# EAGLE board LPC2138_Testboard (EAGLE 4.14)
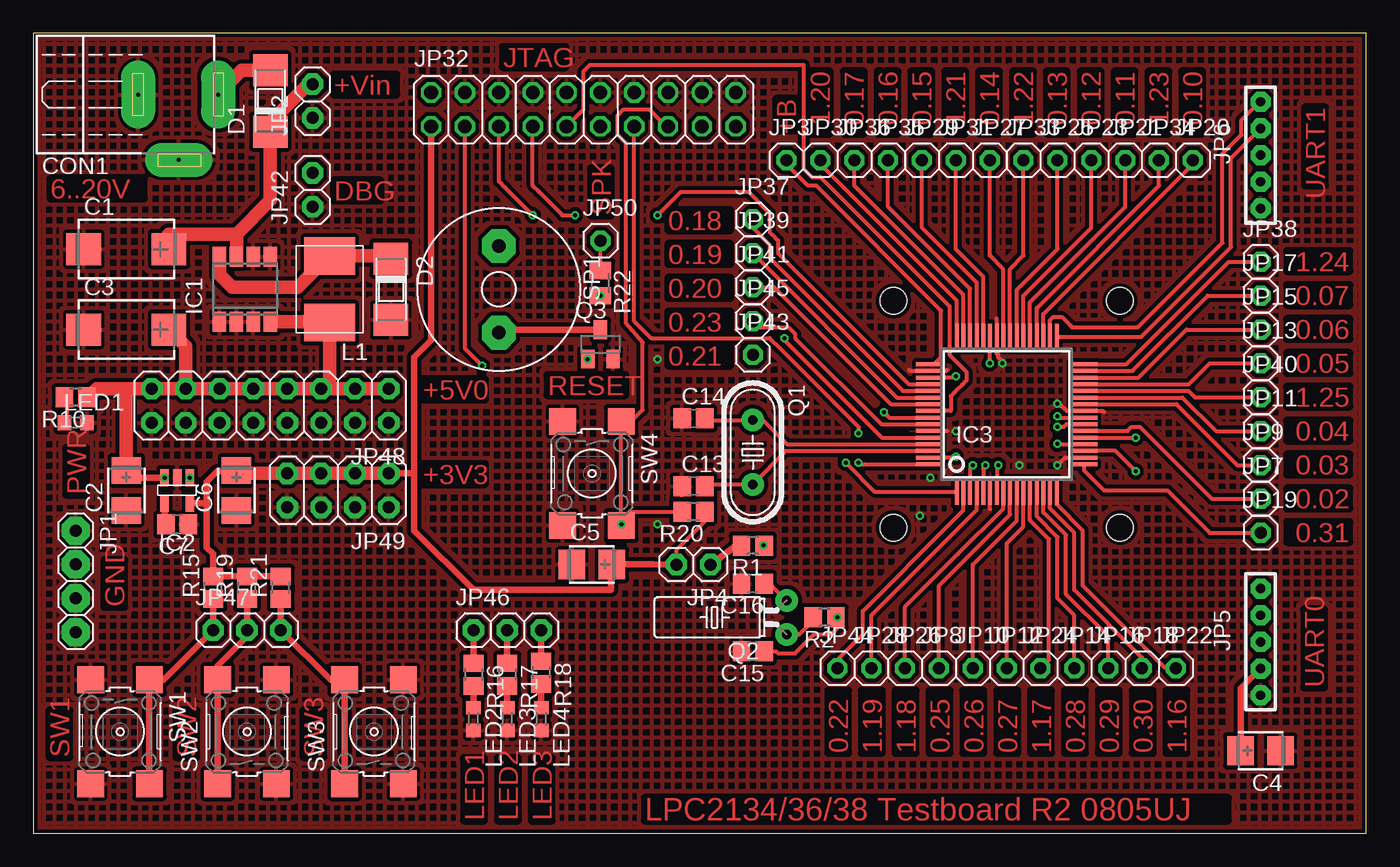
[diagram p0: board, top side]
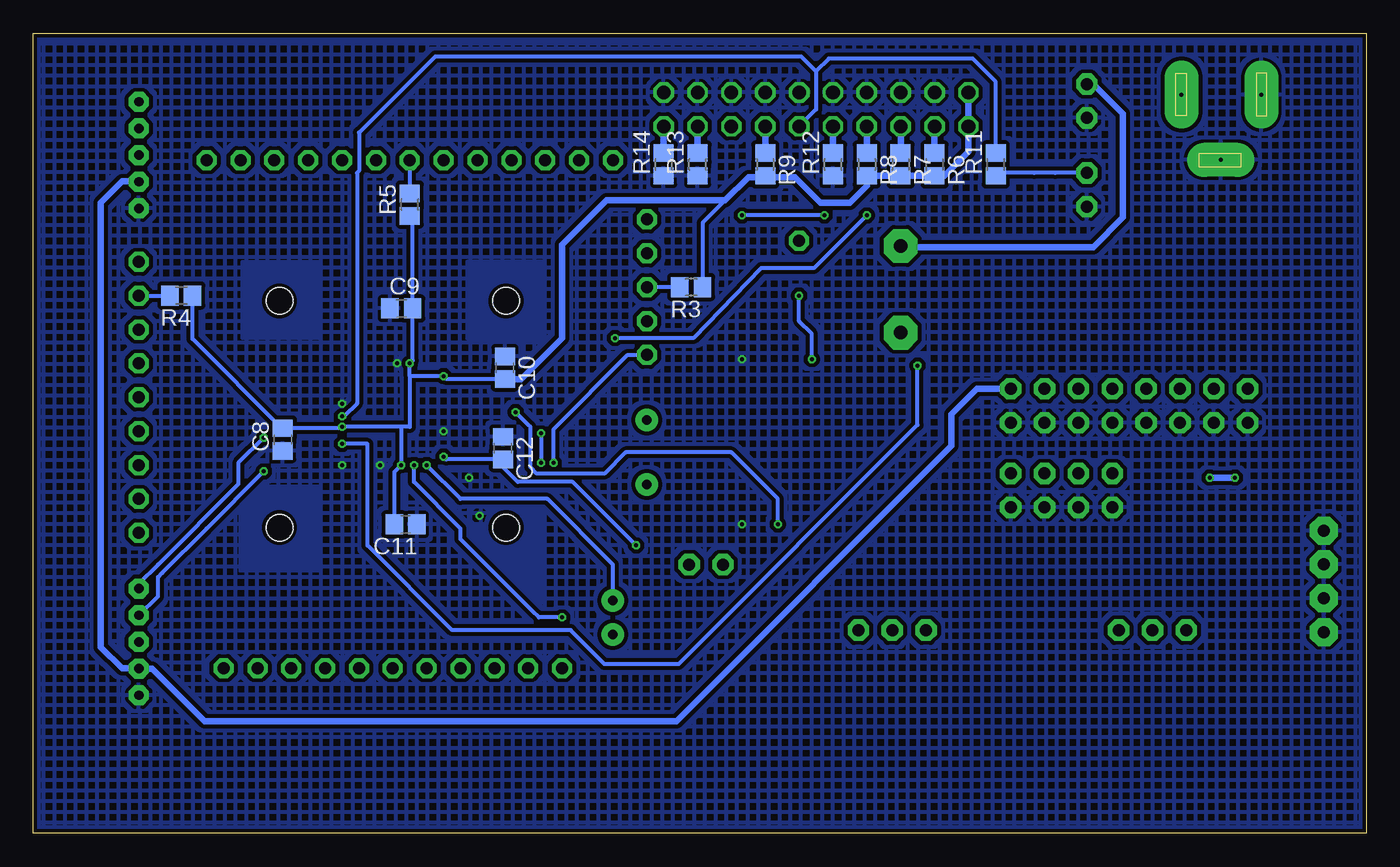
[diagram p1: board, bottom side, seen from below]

Size 100 x 60 mm. Coordinates in mm from the lower left corner, seen from the top.
Outline: 0,0 100,0 100,60 0,60 0,0
Copper layers (1*16): Top 0.035mm / dielectric 1.5mm / Bottom 0.035mm
Design rules "default": minimum track width 0.3mm, minimum drill 0.3mm, track to track 0.3mm, track to pad 0.3mm, pad to pad 0.3mm, via to via 0.3mm, smd to smd 0.3mm, copper to edge 0.3mm, drill to drill 0.3mm, minimum pad ring 10mil, minimum via ring 0.15mm, stop-mask expansion 4mil, vias tented up to drill 0mil, thermal gap 10mil
Net classes: 0 default: width 0.3 mm, drill 0.3 mm, clearance 0.3 mm; 1 power: width 0.6 mm, drill 0.3 mm, clearance 0.6 mm; 2 power_UB: width 1.27 mm, drill 0.25 mm, clearance 0.6 mm

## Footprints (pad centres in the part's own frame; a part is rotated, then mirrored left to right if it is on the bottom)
CT7343 = smd 2.6 x 2.4: + 3.2,0; - -3.2,0
CT3528 = smd 2 x 2.2: + 1.5,0; - -1.5,0
C0805 = smd 1.3 x 1.5: 1 -0.85,0; 2 0.85,0
NEB21R = drill 0.3 pad 2.54 long: + 0,7.35; - 0,1.35; C 4.9,4.4
SOD106A = smd 2.4 x 2.6: A 2.3,0; K -2.3,0
SO8_SMALL = smd 1 x 1.5: 1 -1.905,-2.441; 2 -0.635,-2.441; 3 0.635,-2.441; 4 1.905,-2.441; 5 1.905,2.441; 6 0.635,2.441; 7 -0.635,2.441; 8 -1.905,2.441
SOT23-5 = smd 0.635 x 1.27: 1 -0.953,-0.953; 2 0,-0.953; 3 0.953,-0.953; 4 0.953,0.953; 5 -0.953,0.953
SQFP-S-10X10-64 = smd 0.3 x 2: 1 -3.75,-5.8; 2 -3.25,-5.8; 3 -2.75,-5.8; 4 -2.25,-5.8; 5 -1.75,-5.8; 6 -1.25,-5.8; 7 -0.75,-5.8; 8 -0.25,-5.8; 9 0.25,-5.8; 10 0.75,-5.8; 11 1.25,-5.8; 12 1.75,-5.8; 13 2.25,-5.8; 14 2.75,-5.8; 15 3.25,-5.8; 16 3.75,-5.8; 33 3.75,5.8; 34 3.25,5.8; 35 2.75,5.8; 36 2.25,5.8; 37 1.75,5.8; 38 1.25,5.8; 39 0.75,5.8; 40 0.25,5.8; 41 -0.25,5.8; 42 -0.75,5.8; 43 -1.25,5.8; 44 -1.75,5.8; 45 -2.25,5.8; 46 -2.75,5.8; 47 -3.25,5.8; 48 -3.75,5.8 | smd 2 x 0.3: 17 5.8,-3.75; 18 5.8,-3.25; 19 5.8,-2.75; 20 5.8,-2.25; 21 5.8,-1.75; 22 5.8,-1.25; 23 5.8,-0.75; 24 5.8,-0.25; 25 5.8,0.25; 26 5.8,0.75; 27 5.8,1.25; 28 5.8,1.75; 29 5.8,2.25; 30 5.8,2.75; 31 5.8,3.25; 32 5.8,3.75; 49 -5.8,3.75; 50 -5.8,3.25; 51 -5.8,2.75; 52 -5.8,2.25; 53 -5.8,1.75; 54 -5.8,1.25; 55 -5.8,0.75; 56 -5.8,0.25; 57 -5.8,-0.25; 58 -5.8,-0.75; 59 -5.8,-1.25; 60 -5.8,-1.75; 61 -5.8,-2.25; 62 -5.8,-2.75; 63 -5.8,-3.25; 64 -5.8,-3.75 | hole 2: 8.5,8.5; -8.5,8.5; -8.5,-8.5; 8.5,-8.5
1X04 = drill 0.9 pad 2.1 octagon: 1 -3.81,0; 2 -1.27,0; 3 1.27,0; 4 3.81,0
1X02 = drill 0.9 pad 1.6 octagon: 1 -1.27,0; 2 1.27,0
1X01 = drill 0.9 pad 1.5 octagon: 1 0,0
2.00_1X5 = drill 0.7 pad 1.5 octagon: 1 -6,0; 2 -4,0; 3 -2,0; 4 0,0; 5 2,0
2X10 = drill 1.016 pad 1.5 octagon: 1 -11.43,-1.27; 2 -11.43,1.27; 3 -8.89,-1.27; 4 -8.89,1.27; 5 -6.35,-1.27; 6 -6.35,1.27; 7 -3.81,-1.27; 8 -3.81,1.27; 9 -1.27,-1.27; 10 -1.27,1.27; 11 1.27,-1.27; 12 1.27,1.27; 13 3.81,-1.27; 14 3.81,1.27; 15 6.35,-1.27; 16 6.35,1.27; 17 8.89,-1.27; 18 8.89,1.27; 19 11.43,-1.27; 20 11.43,1.27
1X03 = drill 0.9 pad 1.6 octagon: 1 -2.54,0; 2 0,0; 3 2.54,0
2X08 = drill 0.9 pad 1.6 octagon: 1 -8.89,-1.27; 2 -8.89,1.27; 3 -6.35,-1.27; 4 -6.35,1.27; 5 -3.81,-1.27; 6 -3.81,1.27; 7 -1.27,-1.27; 8 -1.27,1.27; 9 1.27,-1.27; 10 1.27,1.27; 11 3.81,-1.27; 12 3.81,1.27; 13 6.35,-1.27; 14 6.35,1.27; 15 8.89,-1.27; 16 8.89,1.27
2X04 = drill 0.9 pad 1.6 octagon: 1 -3.81,-1.27; 2 -3.81,1.27; 3 -1.27,-1.27; 4 -1.27,1.27; 5 1.27,-1.27; 6 1.27,1.27; 7 3.81,-1.27; 8 3.81,1.27
L5550 = smd 3.8 x 2.8: P$1 0,2.5; P$2 0,-2.5
0603 = smd 1 x 1.1: 1 -0.85,0; 2 0.85,0
HC49/S = drill 0.7 pad 1.7 round: 1 -2.413,0; 2 2.413,0
TC38H = drill 0.7 pad 1.7 round: 1 -1.27,0; 2 1.27,0
SOT23 = smd 1 x 1.4: 1 -0.95,-1.1; 2 0.95,-1.1; 3 0,1.1
R0805 = smd 1.3 x 1.5: 1 -0.85,0; 2 0.85,0
M0805 = smd 1.3 x 1.6: 1 -0.95,0; 2 0.95,0
AL60P = drill 1.016 pad 2.54 octagon: 1 -3.251,0; 2 3.251,0
DIGI_SWITCH = smd 2 x 2: 1 3.9,-2.2; 2 -3.9,-2.2; 3 3.9,2.2; 4 -3.9,2.2

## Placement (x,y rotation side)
C1  100µ  [CT7343]  6.99,43.82 0 top
C2  33µ  [CT3528]  6.99,25.72 90 top
C3  470µ  [CT7343]  6.99,37.78 0 top
C4  10µ  [CT3528]  92.08,6.19 180 top
C5  10µ  [CT3528]  41.91,20.16 0 top
C6  10µ  [CT3528]  15.24,25.72 90 top
C7  100n  [C0805]  10.79,23.18 180 top
C8  220n  [C0805]  81.28,29.53 90 bottom
C9  220n  [C0805]  72.39,39.37 0 bottom
C10  220n  [C0805]  64.61,34.92 270 bottom
C11  220n  [C0805]  72.07,23.18 180 bottom
C12  220n  [C0805]  64.77,28.89 270 bottom
C13  22p  [C0805]  49.53,26.04 0 top
C14  22p  [C0805]  49.53,31.12 0 top
C15  22p  [C0805]  53.98,13.65 180 top
C16  22p  [C0805]  53.98,18.73 180 top
CON1  NEB21R  [NEB21R]  6.51,55.41 270 top
D1  MBR1201  [SOD106A]  17.78,54.93 90 top
D2  MBR1201  [SOD106A]  26.83,40.8 270 top
IC1  LM2594-5  [SO8_SMALL]  15.88,40.8 0 top
IC2  LP2992-3.3  [SOT23-5]  10.79,25.72 180 top
IC3  LPC2138  [SQFP-S-10X10-64]  73.03,31.43 0 top
JP1  [1X04]  3.17,18.89 270 top
JP2  [1X02]  20.95,54.92 90 top
JP3  +BAT  [1X01]  56.52,50.48 0 top
JP4  VREF  [1X02]  49.53,20.16 180 top
JP5  UART0  [2.00_1X5]  92.08,16.35 90 top
JP6  UART1  [2.00_1X5]  92.08,52.86 90 top
JP7  [1X01]  92.08,25.09 0 top
JP8  [1X01]  67.94,12.38 0 top
JP9  [1X01]  92.08,27.62 0 top
JP10  [1X01]  70.48,12.38 0 top
JP11  [1X01]  92.08,30.16 0 top
JP12  [1X01]  73.03,12.38 0 top
JP13  [1X01]  92.08,35.24 0 top
JP14  [1X01]  78.11,12.38 0 top
JP15  [1X01]  92.08,37.78 0 top
JP16  [1X01]  80.64,12.38 0 top
JP17  [1X01]  92.08,40.33 0 top
JP18  [1X01]  83.19,12.38 0 top
JP19  [1X01]  92.08,22.55 0 top
JP20  [1X01]  87,50.48 0 top
JP21  [1X01]  81.92,50.48 0 top
JP22  [1X01]  85.72,12.38 0 top
JP23  [1X01]  79.38,50.48 0 top
JP24  [1X01]  75.56,12.38 0 top
JP25  [1X01]  76.83,50.48 0 top
JP26  [1X01]  65.41,12.38 0 top
JP27  [1X01]  71.75,50.48 0 top
JP28  [1X01]  62.87,12.38 0 top
JP29  [1X01]  66.67,50.48 0 top
JP30  [1X01]  59.05,50.48 0 top
JP31  [1X01]  69.22,50.48 0 top
JP32  JTAG  [2X10]  41.27,54.3 0 top
JP33  [1X01]  74.3,50.48 0 top
JP34  [1X01]  84.45,50.48 0 top
JP35  [1X01]  64.14,50.48 0 top
JP36  [1X01]  61.59,50.48 0 top
JP37  [1X01]  53.98,46.04 0 top
JP38  [1X01]  92.08,42.87 0 top
JP39  [1X01]  53.98,43.5 0 top
JP40  [1X01]  92.08,32.7 0 top
JP41  [1X01]  53.98,40.96 0 top
JP42  DBG  [1X02]  20.95,48.26 90 top
JP43  [1X01]  53.98,35.88 0 top
JP44  [1X01]  60.33,12.38 0 top
JP45  [1X01]  53.98,38.42 0 top
JP46  LED  [1X03]  35.56,15.24 0 top
JP47  [1X03]  16.03,15.24 0 top
JP48  [2X08]  17.78,32.07 180 top
JP49  [2X04]  22.86,25.72 180 top
JP50  [1X01]  42.55,44.45 0 top
L1  100µ  [L5550]  22.23,40.8 180 top
LED1  Grün  [0603]  3.17,30.8 0 top
LED2  Gelb  [0603]  33.02,8.57 270 top
LED3  Gelb  [0603]  35.56,8.57 270 top
LED4  Gelb  [0603]  38.1,8.57 270 top
Q1  10M  [HC49/S]  53.98,28.58 270 top
Q2  32768  [TC38H]  56.52,16.2 90 top
Q3  BC847  [SOT23]  42.55,36.67 0 top
R1  10  [R0805]  53.98,21.59 180 top
R2  560k  [R0805]  59.37,16.2 180 top
R3  10k  [R0805]  50.64,40.96 180 bottom
R4  10k  [R0805]  88.9,40.32 180 bottom
R5  10k  [R0805]  71.75,47.15 90 bottom
R6  [R0805]  32.39,50.16 270 bottom
R7  [R0805]  34.93,50.16 270 bottom
R8  [R0805]  37.47,50.16 270 bottom
R9  [R0805]  45.09,50.16 270 bottom
R10  330  [R0805]  3.17,32.7 180 top
R11  [R0805]  27.78,50.16 90 bottom
R12  [R0805]  40,50.16 90 bottom
R13  [R0805]  50.16,50.16 90 bottom
R14  [R0805]  52.7,50.16 90 bottom
R15  10k  [R0805]  13.49,18.42 90 top
R16  680  [R0805]  33.02,11.91 270 top
R17  680  [R0805]  35.56,11.91 270 top
R18  680  [R0805]  38.1,12.06 270 top
R19  10k  [R0805]  16.03,18.42 90 top
R20  10k  [R0805]  49.53,24.13 180 top
R21  10k  [R0805]  18.57,18.42 90 top
R22  4k7  [M0805]  42.55,41.27 270 top
SP1  AL60P  [AL60P]  34.93,40.8 270 top
SW1  [DIGI_SWITCH]  6.51,7.62 90 top
SW2  [DIGI_SWITCH]  16.03,7.62 270 top
SW3  [DIGI_SWITCH]  25.56,7.62 270 top
SW4  RESET  [DIGI_SWITCH]  41.91,26.99 90 top

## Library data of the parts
C1-C16 R1-R22 = rcl
CON1 JP5 JP6 = Connectors
D1 D2 = telefunken
IC1 IC2 = Power
IC3 = lpc213x
JP1-JP4 JP7-JP50 = PinHeaders
L1 LED1-LED4 = OWN
Q1 Q2 = crystal
Q3 = transistor-npn
SP1 = buzzer
SW1-SW4 = Copter

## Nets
+3V3: C5.+ C6.+ C8.2 C9.2 C10.2 C11.2 IC2.5 IC3.7 IC3.23 IC3.43 IC3.51 JP4.2 JP32.1 JP32.2 JP49.1 JP49.3 JP49.5 JP49.7 R3.1 R4.1 R5.1 R6.2 R7.2 R8.2 R9.2 R15.2 R19.2 R20.1 R21.2
+3V3_VREF: JP4.1 R1.2
+5V: C2.+ C3.+ C4.+ IC1.4 IC2.1 IC2.3 JP5.2 JP6.2 JP48.1 JP48.3 JP48.5 JP48.7 JP48.9 JP48.11 JP48.13 JP48.15 L1.P$1 R10.1
+UB: IC3.49 JP3.1
BP_3V3: C7.2 IC2.4
D2 [power]: D2.K IC1.8 L1.P$2
DBG_RTCK: JP42.2 R11.1
GND: C1.- C2.- C3.- C4.- C5.- C6.- C7.1 C8.1 C9.1 C10.1 C11.1 C12.1 C13.1 C14.1 C15.2 C16.2 CON1.- CON1.C D2.A IC1.1 IC1.2 IC1.3 IC1.5 IC1.6 IC2.2 IC3.6 IC3.18 IC3.25 IC3.42 IC3.50 IC3.59 JP1.1 JP1.2 JP1.3 JP1.4 JP2.1 JP5.1 JP6.1 JP32.4 JP32.6 JP32.8 JP32.10 JP32.12 JP32.14 JP32.16 JP32.18 JP32.20 JP42.1 JP48.2 JP48.4 JP48.6 JP48.8 JP48.10 JP48.12 JP48.14 JP48.16 JP49.2 JP49.4 JP49.6 JP49.8 LED1.2 LED2.2 LED3.2 LED4.2 Q3.2 R12.1 R13.1 R14.1 SW1.3 SW1.4 SW2.3 SW2.4 SW3.3 SW3.4 SW4.3 SW4.4
JTAG_17: JP32.17 R13.2
JTAG_19: JP32.19 R14.2
LED1: JP46.1 R16.1
LED1_A1: LED4.1 R18.2
LED1_A2: LED1.1 R10.2
LED2_A1: LED3.1 R17.2
LED3_A1: LED2.1 R16.2
LED5: JP46.2 R17.1
LED6: JP46.3 R18.1
P0.0_TXD0: IC3.19 JP5.4
P0.1_RXD0: IC3.21 JP5.5
P0.2_SCL0: IC3.22 JP7.1
P0.3_SDA0: IC3.26 JP9.1
P0.4_SCK0: IC3.27 JP11.1
P0.5_MISO0: IC3.29 JP13.1
P0.6_MOSI0: IC3.30 JP15.1
P0.7_SSEL0: IC3.31 JP17.1 R4.2
P0.8_TXD1: IC3.33 JP6.4
P0.9_RXD1: IC3.34 JP6.5
P0.10: IC3.35 JP20.1
P0.11_SCL1: IC3.37 JP21.1
P0.12_MAT1.0: IC3.38 JP23.1
P0.13: IC3.39 JP25.1
P0.14_SDA1: IC3.41 JP27.1 R5.2
P0.15_EINT2: IC3.45 JP29.1
P0.16_EINT0: IC3.46 JP35.1
P0.17_SCK1: IC3.47 JP36.1
P0.18_MISO1: IC3.53 JP37.1
P0.19_MOSI1: IC3.54 JP39.1
P0.20_SSEL1: IC3.55 JP41.1 R3.2
P0.21_PWM5: IC3.1 JP43.1
P0.22: IC3.2 JP44.1
P0.23: IC3.58 JP45.1
P0.25_AD0.4: IC3.9 JP8.1
P0.26_AD0.5: IC3.10 JP10.1
P0.27_AD0.0: IC3.11 JP12.1
P0.28_AD0.1: IC3.13 JP14.1
P0.29_AD0.2: IC3.14 JP16.1
P0.30_AD0.3: IC3.15 JP18.1
P0.31: IC3.17 JP19.1
P1.16: IC3.16 JP22.1
P1.17: IC3.12 JP24.1
P1.18: IC3.8 JP26.1
P1.19: IC3.4 JP28.1
P1.20: IC3.48 JP30.1
P1.21: IC3.44 JP31.1
P1.22: IC3.40 JP33.1
P1.23: IC3.36 JP34.1
P1.24: IC3.32 JP38.1
P1.25: IC3.28 JP40.1
P1.26_RTCK: IC3.24 JP32.11 R11.2
P1.27_TDO: IC3.64 JP32.13 R9.1
P1.28_TDI: IC3.60 JP32.5 R7.1
P1.29_TCK: IC3.56 JP32.9 R12.2
P1.30_TMS: IC3.52 JP32.7 R8.1
P1.31_TRST: IC3.20 JP32.3 R6.1
Q1B: Q3.1 R22.2
RQ: Q2.1 R2.2
RST: IC3.57 JP32.15 R20.2 SW4.1 SW4.2
RTXC1: C16.1 IC3.3 Q2.2
RTXC2: C15.1 IC3.5 R2.1
S1: JP47.3 R21.1 SW3.1 SW3.2
S5: JP47.2 R19.1 SW2.1 SW2.2
S6: JP47.1 R15.1 SW1.1 SW1.2
SPK_GND: Q3.3 SP1.2
SPK_IN: JP50.1 R22.1
VIN [power]: CON1.+ D1.A
VIN_D [power]: C1.+ D1.K IC1.7 JP2.2 SP1.1
VREF: C12.2 IC3.63 R1.1
XTAL1: C13.2 IC3.62 Q1.2
XTAL2: C14.2 IC3.61 Q1.1

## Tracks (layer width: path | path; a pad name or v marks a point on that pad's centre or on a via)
+3V3  (via drill 0.3 pad 0.6)
  Top 0.3: IC3.7 72.28,27.51 v72.39,27.62 | IC3.43 71.78,35.26 v71.75,35.24 | IC3.51 69.11,34.19 v69.22,34.29 | IC3.23 77.52,30.68 77.31,30.48 v76.83,30.48 | R20.1 50.38,23.39 48.26,21.27 JP4.2
  Top 0.5: JP4.2 46.51,20.16 C5.+ 43.41,19.84 43.34,19.84 43.34,18.26 33.02,18.26 28.57,22.7 28.57,26.99 | IC2.5 12.23,24.77 13.02,24.77 | C6.+ 15.08,27.22 15.08,27.15 13.81,27.15 13.02,26.35 13.02,24.77 | R21.2 18.57,19.21 18.52,19.27 R19.2 16.03,19.21 15.97,19.27 R15.2 13.49,20.95 13.02,21.43 13.02,24.77 | JP49.1 28.57,26.99 | JP32.1 29.84,53.18 JP32.1 29.84,52.7 29.84,36.99 28.57,35.72 28.57,26.99
  Top 1: JP49.1 JP49.3 JP49.5 JP49.7 15.4,26.99 15.24,27.15 C6.+
  Bottom 0.3: C11.2 72.92,27.09 v72.39,27.62 72.39,30.48 | C10.2 69,34.08 v69.22,34.29 71.75,34.29 | 72.39,30.48 v76.83,30.48 76.94,30.38 C8.2 81.28,30.32 88.05,37.09 R4.1 | 71.75,34.29 v71.75,35.24 71.54,35.46 C9.2 71.54,46.14 71.75,46.35 | 71.75,34.29 71.75,30.48 72.39,30.48 | R3.1 49.79,45.78 48.1,47.47 | 71.75,46.35 | 71.75,46.35 R5.1
  Bottom 0.5: JP32.2 JP32.1 29.84,51.12 31.65,49.31 R6.2 34.82,49.31 34.92,49.21 34.93,49.21 R7.2 37.36,49.31 37.47,49.21 R8.2 37.47,48.58 38.73,47.31 40.96,47.31 42.86,49.21 45.09,49.21 | C10.2 63.4,34.08 60.33,37.15 60.33,44.13 56.99,47.47 48.1,47.47 46.35,49.21 45.09,49.21 | 45.09,49.21 R9.2
+3V3_VREF
  Top 0.5: R1.2 52.7,21.59 JP4.1
+5V  (via drill 0.3 pad 0.6)
  Top 0.3: IC2.1 | IC2.3 9.68,26.67 IC2.3
  Top 0.5: IC2.3 7.62,26.67 6.99,27.3 | 92.08,12.38 | JP5.2 92.08,12.38 | C4.+ 90.58,10.88 92.08,12.38
  Top 1: JP48.13 11.27,33.34 JP48.15 6.99,33.34 | JP48.13 JP48.11 JP48.9 JP48.7 JP48.5 | JP48.1 JP48.3 JP48.5 | C3.+ 10.32,37.62 11.43,36.51 JP48.13 | R10.1 4.13,32.7 4.76,33.34 6.99,33.34 | C2.+ 6.99,27.3 6.99,33.34 | IC1.4 22.12,38.36 22.23,38.26 L1.P$1 22.23,33.97 JP48.5
  Bottom 0.5: JP48.1 29.21,33.34 31.11,31.43 31.11,29.05 | IC2.3 IC2.1 | 92.08,12.38 | 92.08,12.38 JP5.2 91.09,12.35 87.15,8.41 51.75,8.41 31.11,29.05 | 92.08,12.38 93.34,12.38 94.93,13.97 94.93,47.31 93.34,48.9 92.23,48.9 92.23,48.86 JP6.2 | 31.11,29.05
  other vias: 9.84,26.67 11.75,26.67
+UB
  Top 0.3: IC3.49 67.57,35.19 68.1,35.72 68.1,39.21 58.74,48.58 58.1,48.58 56.52,50.16 JP3.1
BP_3V3
  Top 0.5: 9.84,23.18 | C7.2 9.84,23.18 | 9.84,23.18 IC2.4
D2
  Top 1: IC1.8 13.97,41.91 14.92,40.96 19.84,40.96 22.23,43.34 L1.P$2 26.87,43.3 26.83,43.18 D2.K
DBG_RTCK
  Bottom 0.3: JP42.2 23.34,49.53 24.92,49.53 27.62,49.53 27.78,49.37 R11.1
GND  (via drill 0.3 pad 0.6)
  Top 0.3: IC3.59 68.56,30.18 68.58,30.16 | 72.28,38.62 IC3.42 72.28,35.99 72.39,35.88 72.39,35.72 72.71,35.4 v72.71,35.24 | 68.58,34.77 68.5,34.69 IC3.50 65.8,34.69 65.72,34.77 | IC3.18 77.4,28.18 v76.83,27.62 | 80.33,31.59 80.23,31.68 IC3.25 77.53,31.68 76.99,32.23 v76.83,32.23 | 71.78,24.31 IC3.6
  other vias: 66.52,23.81 67.31,26.67 73.98,27.62 69.22,30.16 46.83,35.56 46.83,23.18
  pour Top (hatched): 0,0 100,0 100,60 0,60
  pour Bottom (hatched): 0,0 100,0 100,60 0,60
JTAG_17
  Bottom 0.5: R13.2 50.16,50.8 | R13.2 | R13.2 JP32.17
JTAG_19
  Bottom 0.5: R14.2 JP32.19
LED1
  Top 0.5: 33.02,12.7 R16.1 JP46.1
LED1_A1
  Top 0.5: 38.1,9.37 LED4.1 R18.2
LED1_A2
  Top 0.3: LED1.1 2.54,30.48 2.54,33.02 R10.2
LED2_A1
  Top 0.5: LED3.1 R17.2
LED3_A1
  Top 0.5: 33.02,9.37 LED2.1 R16.2
LED5
  Top 0.5: 35.56,12.7 R17.1 JP46.2
LED6
  Top 0.5: 38.1,12.86 R18.1 JP46.3
N$6
  pour Bottom: 61.75,42.86 67.47,42.86 67.47,37.15 61.75,37.15
N$7
  pour Bottom: 78.58,42.86 78.58,37.15 84.3,37.15 84.3,42.86
N$8
  pour Bottom: 78.58,26.04 78.58,19.68 84.45,19.68 84.45,24.45 82.87,26.04
N$9
  pour Bottom: 61.75,24.45 61.75,17.3 62.23,17.3 67.31,22.38 67.31,24.45
P0.0_TXD0  (via drill 0.3 pad 0.6)
  Top 0.3: IC3.19 81.17,28.68 v82.71,27.15
  Bottom 0.3: v82.71,27.15 87,22.86 90.33,19.53 | 90.33,19.53 | 90.33,19.53 90.65,19.21 90.65,17.78 JP5.4 | JP5.4 | JP5.4
P0.1_RXD0  (via drill 0.3 pad 0.6)
  Top 0.3: IC3.21 v82.71,29.68 v82.71,29.69
  Bottom 0.3: v82.71,29.69 84.61,27.78 84.61,26.19 90.65,20.16 92.08,18.73 | 92.08,18.73 | 92.08,18.73 JP5.5
P0.2_SCL0
  Top 0.3: IC3.22 82.1,30.18 82.39,30.48 83.03,30.48 88.42,25.08 JP7.1
P0.3_SDA0
  Top 0.3: IC3.26 85.77,32.19 90.33,27.62 JP9.1
P0.4_SCK0
  Top 0.3: IC3.27 86.22,32.69 88.74,30.16 JP11.1
P0.5_MISO0
  Top 0.3: IC3.29 86.71,33.69 88.27,35.24 JP13.1
P0.6_MOSI0
  Top 0.3: IC3.30 82.92,34.19 86.52,37.78 JP15.1
P0.7_SSEL0
  Top 0.3: IC3.31 82.47,34.69 88.11,40.32 JP17.1
  Bottom 0.3: JP17.1 | JP17.1 R4.2 | JP17.1
P0.8_TXD1
  Top 0.3: IC3.33 83.11,37.23 89.85,43.97 89.85,50.64 90.33,51.12 JP6.4 | JP6.4 | JP6.4
P0.9_RXD1
  Top 0.3: IC3.34 76.28,38.49 76.52,38.73 77.15,38.73 77.79,38.1 77.95,37.94 82.87,37.94 89.22,44.29 89.22,50.96 90.65,52.39 90.65,53.5 91.92,54.77 JP6.5
P0.10
  Top 0.3: IC3.35 75.78,38.95 87,50.16 JP20.1
P0.11_SCL1
  Top 0.3: IC3.37 74.78,39.85 81.92,46.99 JP21.1
P0.12_MAT1.0
  Top 0.3: IC3.38 74.28,40.3 79.38,45.4 JP23.1
P0.13
  Top 0.3: IC3.39 73.78,40.76 76.83,43.81 JP25.1
P0.14_SDA1
  Top 0.3: IC3.41 72.78,42.32 71.75,43.34 JP27.1
  Bottom 0.3: JP27.1 | JP27.1 R5.2 | JP27.1
P0.15_EINT2
  Top 0.3: IC3.45 70.78,41.3 66.67,45.4 JP29.1
P0.16_EINT0
  Top 0.3: IC3.46 70.28,40.85 64.14,46.99 JP35.1
P0.17_SCK1
  Top 0.3: IC3.47 69.78,40.4 61.59,48.58 JP36.1
P0.18_MISO1
  Top 0.3: IC3.53 65.24,33.19 55.24,43.18 55.24,44.13 53.98,45.4 JP37.1
P0.19_MOSI1
  Top 0.3: JP39.1 53.98,43.34 54.13,43.34 64.79,32.69 IC3.54
P0.20_SSEL1
  Top 0.3: IC3.55 64.33,32.19 55.56,40.96 JP41.1
  Bottom 0.3: JP41.1 | R3.2 JP41.1 | JP41.1
P0.21_PWM5  (via drill 0.3 pad 0.6)
  Top 0.3: IC3.1 63.11,25.64 v60.96,27.78
  Bottom 0.3: v60.96,27.78 60.96,30.32 55.4,35.88 JP43.1
P0.22
  Top 0.3: IC3.2 69.78,24.21 68.9,23.34 62.23,16.67 62.23,14.92 60.33,13.02 60.33,12.54 JP44.1
P0.23
  Top 0.3: IC3.58 63.61,30.68 57.15,37.15 57.15,37.47 56.67,37.94 54.45,37.94 JP45.1
P0.25_AD0.4
  Top 0.3: IC3.9 73.28,23.9 67.94,18.57 JP8.1
P0.26_AD0.5
  Top 0.3: IC3.10 73.78,23.45 70.48,20.16 JP10.1
P0.27_AD0.0
  Top 0.3: IC3.11 74.28,23 73.03,21.75 JP12.1
P0.28_AD0.1
  Top 0.3: IC3.13 75.28,23.79 76.83,22.23 76.83,17.62 78.11,16.35 JP14.1
P0.29_AD0.2
  Top 0.3: IC3.14 75.78,24.08 77.47,22.38 77.47,17.94 80.64,14.76 JP16.1
P0.30_AD0.3
  Top 0.3: IC3.15 76.28,24.37 78.11,22.54 78.11,18.26 83.19,13.18 JP18.1
P0.31
  Top 0.3: JP19.1 88.27,22.54 85.09,25.72 80.33,25.72 78.83,27.22 IC3.17
P1.16
  Top 0.3: IC3.16 76.78,24.67 78.74,22.7 78.74,18.57 84.93,12.38 JP22.1
P1.17
  Top 0.3: IC3.12 74.78,23.49 76.2,22.07 76.2,13.02 JP24.1
P1.18
  Top 0.3: IC3.8 72.78,24.36 69.37,20.95 65.41,16.99 JP26.1
P1.19
  Top 0.3: IC3.4 70.78,24.26 62.87,16.35 JP28.1
P1.20
  Top 0.3: JP30.1 59.05,50.16 69.28,39.95 IC3.48
P1.21
  Top 0.3: IC3.44 71.28,41.76 69.22,43.81 JP31.1
P1.22
  Top 0.3: IC3.40 73.28,42.32 74.3,43.34 JP33.1
P1.23
  Top 0.3: IC3.36 75.28,39.4 84.45,48.58 JP34.1
P1.24
  Top 0.3: IC3.32 82.02,35.19 89.69,42.86 JP38.1
P1.25
  Top 0.3: IC3.28 86.67,33.19 87.15,32.7 91.92,32.7 JP40.1
P1.26_RTCK  (via drill 0.3 pad 0.6)
  Top 0.3: IC3.24 76.92,31.18 v76.83,31.27
  Bottom 0.3: 41.27,57.15 40.33,58.1 29.52,58.1 27.78,56.36 27.78,50.96 R11.2 | 41.27,57.15 41.27,54.29 JP32.11 | v76.83,31.27 76.68,31.27 75.72,32.23 75.72,49.53 75.56,49.69 75.56,52.55 69.85,58.26 42.39,58.26 41.27,57.15
  Bottom 0.5: JP32.11
P1.27_TDO  (via drill 0.3 pad 0.6)
  Top 0.3: IC3.64 62.01,27.68 v61.91,27.78 | v61.91,30 61.91,30.48 56.2,36.2 56.04,36.35 55.24,37.15 46.35,37.15 45.09,38.42 JP32.13
  Bottom 0.3: v61.91,30 v61.91,27.78
  Bottom 0.5: R9.1 JP32.13
P1.28_TDI  (via drill 0.3 pad 0.6)
  Top 0.3: IC3.60 63.66,29.68 56.36,36.99 v56.36,37.15 | v37.47,46.35 35.4,48.42 34.92,48.9 JP32.5
  Bottom 0.3: v56.36,37.15 53.02,37.15 50.48,37.15 45.4,42.39 41.43,42.39 v37.47,46.35
  Bottom 0.5: R7.1 JP32.5
P1.29_TCK
  Top 0.3: IC3.56 68.83,31.68 68.83,32.8 69.06,33.02 69.22,33.18 69.69,33.66 70.01,33.97 70.01,34.61 68.74,35.88 68.74,39.53 59.05,49.21 58.42,49.21 57.78,49.85 57.78,57.63 41.75,57.63 41.27,57.15 41.27,54.29 JP32.9
  Bottom 0.5: JP32.9 40.01,52.86 40,52.86 R12.2
P1.30_TMS  (via drill 0.3 pad 0.6)
  Top 0.3: IC3.52 65.69,33.69 55.88,43.5 55.88,44.45 55.4,44.93 55.24,45.09 55.24,46.51 53.66,48.1 48.58,48.1 v46.83,46.35 | v40.64,46.35 39.69,46.35 37.94,48.1 37.47,48.58 JP32.7
  Bottom 0.3: v40.64,46.35 v46.83,46.35
  Bottom 0.5: R8.1 JP32.7
P1.31_TRST  (via drill 0.3 pad 0.6)
  Top 0.3: IC3.20 76.86,29.18 v76.83,29.21 | v33.66,35.08 32.38,36.35 JP32.3
  Bottom 0.3: v33.66,35.08 33.66,30.64 51.59,12.7 57.15,12.7 59.69,15.24 68.58,15.24 74.93,21.59 74.93,29.21 v76.83,29.21
  Bottom 0.5: R6.1 JP32.3
Q1B  (via drill 0.3 pad 0.6)
  Top 0.3: 43.18,40.16 R22.2 | Q3.1 v41.59,35.56
  Bottom 0.3: R22.2 42.55,38.42 41.59,37.47 v41.59,35.56
  other vias: 42.55,40.32
RQ
  Top 0.3: R2.2 58.74,16.2 58.74,16.19 57.47,14.93 Q2.1
RST  (via drill 0.3 pad 0.6)
  Top 0.3: IC3.57 64.22,31.18 v63.82,31.59 | v44.13,23.18 44.11,23.2 SW4.1 44.11,30.96 44.13,30.16 45.72,31.75 45.72,36.83 44.45,38.26 44.45,51.75 43.81,52.39 43.81,53.82 44.29,54.29 46.2,54.29 47.46,53.02 JP32.15 | SW4.2 44.11,23.34 44.13,23.34 v44.13,23.18 | R20.2 44.77,24.13 v44.13,23.18
  Bottom 0.3: v63.82,31.59 | v63.82,31.59 62.87,30.64 62.71,30.48 62.71,27.46 62.23,26.99 57.15,26.99 55.56,28.57 47.62,28.57 44.13,25.08 v44.13,23.18
RTXC1  (via drill 0.3 pad 0.6)
  Top 0.3: Q2.2 55.24,18.73 C16.1 | IC3.3 70.28,27.41 v70.48,27.62
  Bottom 0.3: Q2.2 56.52,20.16 61.44,25.08 67.94,25.08 v70.48,27.62
RTXC2  (via drill 0.3 pad 0.6)
  Top 0.3: IC3.5 71.28,27.31 v71.44,27.62 | C15.1 55.72,13.65 55.88,13.49 57.15,13.49 58.58,14.92 59.85,14.92 60.33,15.4 v60.33,16.19 60.17,16.2 R2.1
  Bottom 0.3: v60.33,16.19 62.07,16.19 62.55,16.67 67.94,22.07 67.94,22.86 71.44,26.35 71.44,26.51 v71.44,27.62
S1
  Top 0.5: SW3.1 23.36,3.81 23.34,3.81 23.36,3.83 SW3.2 22.29,11.52 JP47.3 | JP47.3 | JP47.3 R21.1
S5
  Top 0.5: SW2.1 13.83,11.41 13.81,11.43 13.83,11.43 SW2.2 13.83,12.56 16.03,14.76 16.03,15.56 | JP47.2 16.03,15.56 | 16.03,15.56 R19.1
S6
  Top 0.5: SW1.1 8.71,11.59 8.73,11.59 8.71,11.57 SW1.1 | SW1.2 SW1.1 | SW1.1 9.78,11.52 JP47.1 | JP47.1 | JP47.1 R15.1
SPK_GND
  Top 0.5: 34.92,37.62 | SP1.2 34.92,37.62 | Q3.3 35.07,37.77 34.92,37.62
SPK_IN
  Top 0.3: JP50.1 | R22.1 JP50.1
VIN
  Top 1: CON1.+ 13.81,55.41 13.97,55.56 15.64,57.23 D1.A
VIN_D
  Top 1: JP2.2 20.64,56.2 17.78,53.34 D1.K 17.78,47.47 15.24,44.93 | 15.24,44.93 IC1.7 | C1.+ 10.19,43.84 10.16,44.93 15.24,44.93
  Bottom 0.5: JP2.2 20.48,56.2 18.26,53.98 18.26,46.2 20.48,43.97 34.92,43.97 SP1.1
VREF  (via drill 0.3 pad 0.6)
  Top 0.3: IC3.63 69.14,28.18 v69.22,28.26
  Top 0.5: R1.1 v54.77,21.59
  Bottom 0.3: v69.22,28.26 69,28.04 C12.2 64.77,28.1 64.77,27.46 63.66,26.35 59.53,26.35 v54.77,21.59
XTAL1
  Top 0.3: 53.98,26.19 Q1.2 | IC3.62 56.47,28.68 53.98,26.19 | C13.2 50.48,26.04 50.64,26.19 53.98,26.19
XTAL2
  Top 0.3: IC3.61 56.54,29.18 54.77,30.96 Q1.1 50.61,30.99 50.48,31.11 50.48,31.12 C14.2

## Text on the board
Top: JTAG | 1.20 | 0.17 | 0.16 | 0.15 | 1.21 | 0.14 | 1.22 | 0.13 | 0.12 | 0.11 | 1.23 | 0.10 | +Vin | +B | UART1 | 6..20V | DBG | SPK | 0.18 | 1.24 | 0.19 | 0.07 | 0.20 | 0.06 | 0.23 | 0.05 | 0.21 | +5V0 | RESET | 1.25 | 0.04 | 0.03 | +3V3 | 0.02 | PWR | 0.31 | GND | UART0 | SW1 | SW2 | SW3 | 0.22 | 1.19 | 1.18 | 0.25 | 0.26 | 0.27 | 1.17 | 0.28 | 0.29 | 0.30 | 1.16 | LED1 | LED2 | LED3 | LPC2134/36/38 Testboard R2 0805UJ
tStop: JTAG | 1.20 | 0.17 | 0.16 | 0.15 | 1.21 | 0.14 | 1.22 | 0.13 | 0.12 | 0.11 | 1.23 | 0.10 | +Vin | +B | UART1 | 6..20V | DBG | SPK | 0.18 | 1.24 | 0.19 | 0.07 | 0.20 | 0.06 | 0.23 | 0.05 | 0.21 | +5V0 | RESET | 1.25 | 0.04 | 0.03 | +3V3 | 0.02 | PWR | 0.31 | GND | UART0 | SW1 | SW2 | SW3 | 0.22 | 1.19 | 1.18 | 0.25 | 0.26 | 0.27 | 1.17 | 0.28 | 0.29 | 0.30 | 1.16 | LED1 | LED2 | LED3 | LPC2134/36/38 Testboard R2 0805UJ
